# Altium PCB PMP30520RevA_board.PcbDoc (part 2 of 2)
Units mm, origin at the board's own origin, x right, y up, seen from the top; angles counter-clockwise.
Board outline 53.34 x 64.26 mm, 2 copper layers (Top Layer, Bottom Layer), stack 1.575 mm thick; 53 components, 27 nets, 127 pads, 140 vias.
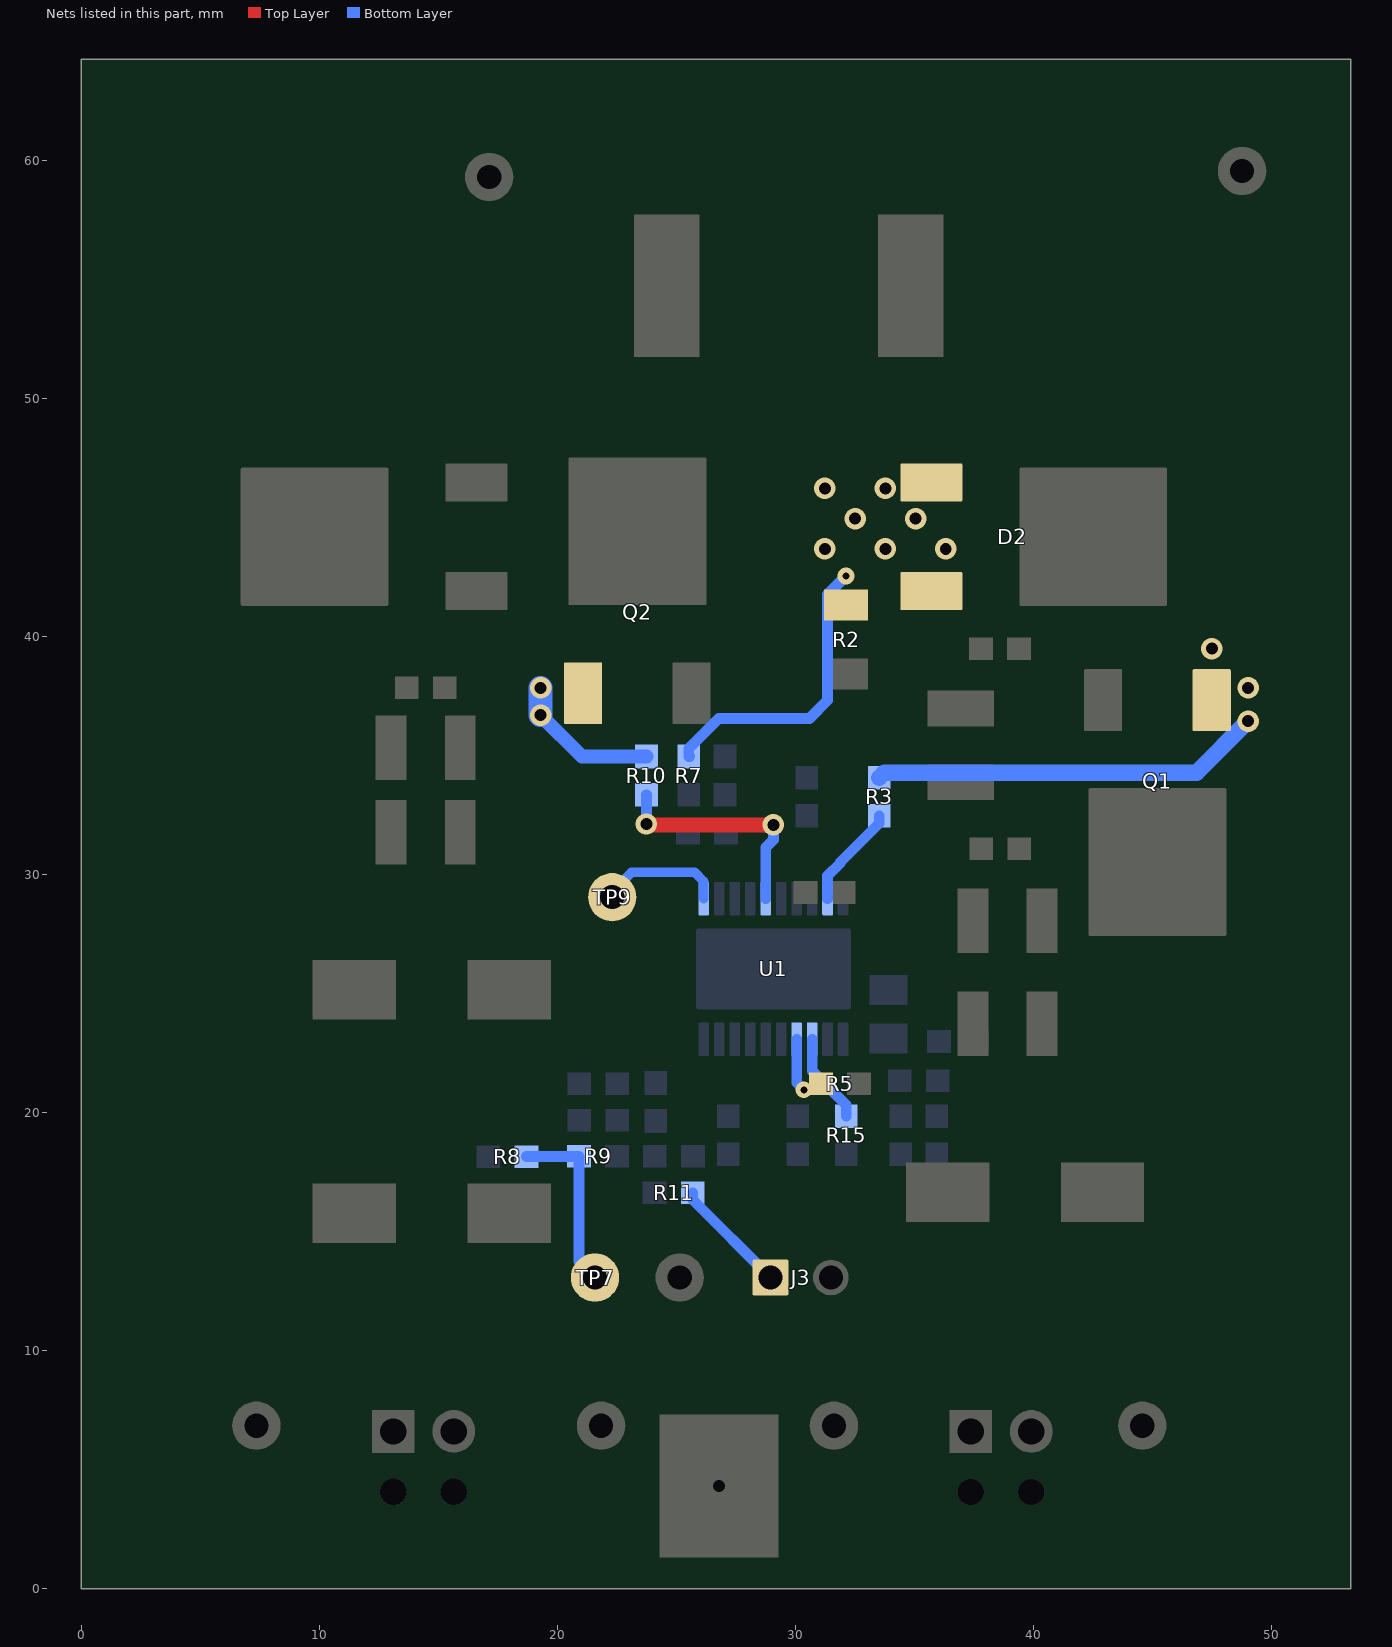
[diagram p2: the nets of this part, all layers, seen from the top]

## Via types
v1: diameter 0.9, hole 0.5, Top Layer to Bottom Layer, 60 vias
v2: diameter 0.7, hole 0.3, Top Layer to Bottom Layer, 34 vias
v3: diameter 0.9, hole 0.5, Top Layer to Bottom Layer, tented top, 25 vias
v4: diameter 0.6, hole 0.3, Top Layer to Bottom Layer, 9 vias
v5: diameter 0.6, hole 0.3, Top Layer to Bottom Layer, tented both sides, 6 vias
v6: diameter 0.9, hole 0.5, Top Layer to Bottom Layer, tented bottom, 2 vias
v7: diameter 0.7, hole 0.3, Top Layer to Bottom Layer, tented both sides, 2 vias
v8: diameter 0.7, hole 0.3, Top Layer to Bottom Layer, tented bottom, 1 vias
v9: diameter 0.9, hole 0.5, Top Layer to Bottom Layer, tented both sides, 1 vias

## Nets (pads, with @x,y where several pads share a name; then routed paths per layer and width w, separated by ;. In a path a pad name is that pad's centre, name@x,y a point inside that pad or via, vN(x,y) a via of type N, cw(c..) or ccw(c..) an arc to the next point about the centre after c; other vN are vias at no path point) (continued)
NetD2_1: D2.1 D2.3 R2.1 R7.2 | length 12.6
  Bottom Layer w0.45: R7.2@25.565,34.963 R7.2@25.527,34.963 25.527,35.306 26.787,36.566 30.597,36.566 31.356,37.325 31.356,41.77 v2(32.131,42.545)
  other v1: 31.242,43.688 33.782,43.688 36.322,43.688 32.512,44.958 35.052,44.958 31.242,46.228
  other v3: 33.782,46.228
NetJ3_1: J3.1 R11.2 | length 4.9
  Bottom Layer w0.45: R11.2@25.692,16.637 25.692,16.345 J3.1@28.956,13.081
NetQ1_1: Q1.1 R3.2 | length 16.5
  Bottom Layer w0.7: R3.2@33.528,34.074 33.744,34.29 46.863,34.29 v1(49.022,36.449)
  other v1: 49.022,37.846 47.498,39.497
NetQ2_1: Q2.1 R10.1 | length 6.3
  Bottom Layer w0.6: v1(19.304,36.703) 21.044,34.963 R10.1@23.749,34.963
  Bottom Layer w1: v1(19.304,36.703) v1(19.304,37.846)
NetR3_1: R3.1 U1.19 | length 4.4
  Bottom Layer w0.45: U1.19@31.358,28.993 31.358,29.961 31.885,30.488 31.885,30.521 33.528,32.164 R3.1@33.528,32.474
NetR5_1: R5.1 U1.4 | length 3.1
  Top Layer w0.45: v7(30.361,20.963) 30.823,20.963 R5.1@31.077,21.217
  Bottom Layer w0.45: U1.4@30.058,23.093 30.058,21.266 v7(30.361,20.963)
NetR8_1: R8.1 R9.2 TP7.1 | length 7.6
  Bottom Layer w0.45: R8.1@18.707,18.161 20.909,18.161 R9.2@20.917,18.169 20.917,13.754 TP7.1@21.59,13.081
NetR10_2: R10.2 U1.15 | length 9.8
  Top Layer w0.635: v1(23.749,32.131) 23.787,32.093 v1(29.083,32.093)
  Bottom Layer w0.45: v1(23.749,32.131) R10.2@23.749,33.363 ; U1.15@28.758,28.993 28.758,31.145 29.083,31.47 v1(29.083,32.093)
NetR15_2: R15.2 U1.3 | length 3.8
  Bottom Layer w0.45: U1.3@30.708,23.093 30.708,21.759 32.139,20.328 R15.2@32.139,19.858
NetTP9_1: TP9.1 U1.11 | length 5.3
  Bottom Layer w0.4: TP9.1@22.313,29.059 22.313,29.298 23.114,30.099 25.781,30.099 26.158,29.722 U1.11@26.158,28.993
pads on no net: J1.MH1 J1.MH2 J2.MH1 J2.MH2 U1.21@29.083,26.043

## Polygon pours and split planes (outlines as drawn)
NetC4_1 on Top Layer "TOP_LAYER_NETC4_1_P006" (solid, remove dead copper, pour order 6): 30.734,49.911 ccw(c32.258,49.911) 32.258,48.387 37.465,48.387 cw(c37.452,46.999) 38.839,46.986 cw(c37.465,46.736) 38.862,46.736 38.862,40.359 38.862,36.576 ccw(c39.751,36.576) 39.751,35.687 41.656,35.687 44.196,35.687 45.085,35.687 ccw(c45.085,36.195) 45.593,36.195 45.593,40.259 cw(c46.609,40.259) 46.609,41.275 48.641,41.275 ccw(c48.641,43.434) 50.8,43.434 50.8,59.309 ccw(c48.514,59.309) 48.514,61.595 33.02,61.595 ccw(c33.02,59.309) 30.734,59.309
NetQ2_1 on Top Layer "TOP_LAYER_NETQ2_1_P018" (solid, remove dead copper, pour order 18): 22.098,39.243 22.098,35.941 18.669,35.941 18.669,39.243
NetQ1_1 on Top Layer "TOP_LAYER_NETQ1_1_P042" (solid, remove dead copper, pour order 42): 47.371,35.814 46.986,35.814 cw(c46.982,36.187) 46.609,36.182 46.609,39.624 cw(c47.244,39.624) 47.244,40.259 47.371,40.259 50.038,40.259 cw(c50.038,39.497) 50.8,39.497 50.8,36.83 cw(c49.784,36.83) 49.784,35.814 49.53,35.814
NetC2_1 on Top Layer "TOP_LAYER_NETC2_1_P002" (solid, remove dead copper, pour order 2): 14.224,2.667 2.54,2.667 2.54,61.595 14.224,61.595 14.224,38.481 14.224,6.529
NetD1_1 on Top Layer "TOP_LAYER_NETD1_1_P004" (solid, remove dead copper, pour order 4): 17.78,61.595 ccw(c17.78,59.055) 15.24,59.055 15.24,41.021 ccw(c16.129,41.021) 16.129,40.132 26.416,40.132 28.067,40.132 ccw(c28.067,41.783) 29.718,41.783 29.718,59.055 ccw(c27.178,59.055) 27.178,61.595
NetD2_1 on Top Layer "TOP_LAYER_NETD2_1_P012" (solid, remove dead copper, pour order 12): 37.616,46.609 ccw(c36.854,46.609) 36.854,47.371 32.258,47.371 31.487,47.362 ccw(c31.487,46.609) 30.734,46.609 30.734,41.275 ccw(c31.369,41.275) 31.369,40.64 36.83,40.64 ccw(c36.83,41.426) 37.616,41.426
NetC1_1 on Top Layer "TOP_LAYER_NETC1_1_P016" (solid, remove dead copper, pour order 16): 38.862,34.671 50.8,34.671 50.8,2.667 38.862,2.667
GND on Top Layer "TOP_LAYER_GND_P020" (solid, remove dead copper, pour order 20): 38.354,2.667 38.354,34.671 34.925,34.671 34.925,39.243 14.732,39.243 14.732,33.909 14.732,4.953 14.732,2.667
NetC4_2 on Top Layer "TOP_LAYER_NETC4_2_P028" (solid, remove dead copper, pour order 28): 38.346,36.195 35.56,36.195 35.56,40.222 38.346,40.222 38.346,38.608
NetD1_1 on Bottom Layer "BOTTOM_LAYER_NETD1_1_P060" (solid, remove dead copper, pour order 60): 17.78,61.595 ccw(c17.78,59.055) 15.24,59.055 15.24,41.021 ccw(c16.129,41.021) 16.129,40.132 26.416,40.132 28.067,40.132 ccw(c28.067,41.783) 29.718,41.783 29.718,59.055 ccw(c27.178,59.055) 27.178,61.595
NetD2_1 on Bottom Layer "BOTTOM_LAYER_NETD2_1_P058" (solid, remove dead copper, pour order 58): 37.616,46.609 ccw(c36.854,46.609) 36.854,47.371 32.258,47.371 31.487,47.362 ccw(c31.487,46.609) 30.734,46.609 30.734,41.275 ccw(c31.369,41.275) 31.369,40.64 36.83,40.64 ccw(c36.83,41.426) 37.616,41.426
NetC4_1 on Bottom Layer "BOTTOM_LAYER_NETC4_1_P056" (solid, remove dead copper, pour order 56): 30.734,49.911 ccw(c32.258,49.911) 32.258,48.387 37.465,48.387 cw(c37.452,46.999) 38.839,46.986 cw(c37.465,46.736) 38.862,46.736 38.862,40.359 38.862,36.576 ccw(c39.751,36.576) 39.751,35.687 41.656,35.687 44.196,35.687 45.085,35.687 ccw(c45.085,36.195) 45.593,36.195 45.593,40.259 cw(c46.609,40.259) 46.609,41.275 49.022,41.275 cw(c49.022,40.259) 50.038,40.259 ccw(c50.038,41.021) 50.8,41.021 50.8,43.688 50.8,59.309 ccw(c48.514,59.309) 48.514,61.595 33.02,61.595 ccw(c33.02,59.309) 30.734,59.309
NetQ1_1 on Bottom Layer "BOTTOM_LAYER_NETQ1_1_P050" (solid, remove dead copper, pour order 50): 46.6,36.2 ccw(c46.986,36.2) 46.986,35.814 48.387,35.814 ccw(c48.387,36.449) 49.022,36.449 49.022,39.869 ccw(c48.637,39.874) 48.641,40.259 47.244,40.259 ccw(c47.244,39.615) 46.6,39.615
NetC16_2 on Bottom Layer "BOTTOM_LAYER_NETC16_2_P022" (solid, remove dead copper, pour order 22): 24.701,17.653 24.701,20.152 22.034,20.152 22.034,17.653
GND on Bottom Layer "BOTTOM_LAYER_GND_P024" (solid, remove dead copper, pour order 24): 34.925,39.243 34.925,34.671 38.354,34.671 38.354,8.382 14.732,8.382 14.732,39.243
GND on Bottom Layer "BOTTOM_LAYER_GND_P026" (solid, remove dead copper, pour order 26): 21.971,24.333 21.971,27.737 36.195,27.737 36.195,24.333
NetC1_1 on Bottom Layer "BOTTOM_LAYER_NETC1_1_P030" (solid, remove dead copper, pour order 30): 38.862,34.674 50.927,34.674 50.927,2.67 38.862,2.67
NetC2_1 on Bottom Layer "BOTTOM_LAYER_NETC2_1_P038" (solid, remove dead copper, pour order 38): 14.224,2.667 2.54,2.667 2.54,61.595 14.224,61.595 14.224,38.481 14.224,6.529

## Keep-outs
Keep-Out Layer:
  text ".Layer_Name" at 14.656,-21.806 h1.52

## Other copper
Top Layer:
  rectangle net NetC4_2: 35.56,36.195 38.354,40.222
  text ".Layer_Name" at 14.656,-21.806 h1.52
Bottom Layer:
  region net NetQ1_1: 49.022,35.814 ccw(c49.022,36.322) 49.53,36.322 49.53,39.649 ccw(c48.92,39.649) 48.92,40.259 48.006,40.259 48.006,36.576 ccw(c48.768,36.576) 48.768,35.814
  pour cut-out: 25.604,24.181 32.715,24.181 32.715,23.623 25.606,23.623
  pour cut-out: 25.629,28.575 25.629,27.889 32.995,27.889 32.995,28.559
  pour cut-out: 28.542,35.306 31.623,35.306 32.893,36.576 32.893,38.1 31.75,38.1 30.099,36.449 27.051,36.449 27.051,34.765 27.526,34.29
  text ".Layer_Name" at 14.656,-21.806 h1.52

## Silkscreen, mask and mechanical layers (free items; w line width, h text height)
Top Overlay:
  lines w0.254: 32.765,13.081 34.29,13.081 34.29,11.43 ; 33.401,11.43 35.179,11.43 ; 33.655,11.049 34.925,11.049 ; 33.909,10.668 34.671,10.668
  text "'.PRJ_Number''.PCB_Rev'" at 51.689,5.207 h2 r90
  text "+VOUT" at 2.413,0.635 h1.52
  text "+VIN" at 43.434,0.635 h1.52
  text ".Layer_Name" at 14.656,-21.806 h1.52
Bottom Overlay:
  text ".Layer_Name" at 14.656,-21.806 h1.52
Top Paste:
  text ".Layer_Name" at 14.656,-21.806 h1.52
Bottom Paste:
  text ".Layer_Name" at 14.656,-21.806 h1.52
Top Solder:
  text ".Layer_Name" at 14.656,-21.806 h1.52
  text ".Layer_Name" at 14.656,-21.806 h1.52
Bottom Solder:
  text "'.PRJ_Number''.PCB_Rev'" at 35.052,8.763 h2
  text ".Layer_Name" at 14.656,-21.806 h1.52
Drill Guide:
  text ".Layer_Name" at 14.656,-21.806 h1.52
M1 Board Outline:
  the board outline again, w0.254
  text ".Layer_Name" at 14.656,-21.806 h1.52
M2 Board Dimensions:
  rectangle: 3.175,-10.16 12.7,-6.985
  rectangle: 0,-6.985 3.175,-3.81
  lines w0.178: 0,-6.985 25.4,-6.985 ; 3.175,-10.16 3.175,-3.81 ; 6.35,-10.16 6.35,-3.81 ; 12.7,-10.16 12.7,-3.81 ; 19.05,-10.16 19.05,-3.81 ; 0,-10.16 0,-3.81 25.4,-3.81 25.4,-10.16 0,-10.16
  text "'.Print_Date'" at 1.778,64.77 h1.52
  text "'.Print_Time'" at 16.891,64.77 h1.52
  text ".Layer_Name" at 14.656,-21.806 h1.52
M3 3D STEP Top:
  text ".Layer_Name" at 14.656,-21.806 h1.52
M4 3D STEP Bottom:
  text ".Layer_Name" at 14.656,-21.806 h1.52
M5 Assembly Top:
  lines w0.254: -7.417,-23.626 160.223,-23.626 ; -7.417,-18.462 160.274,-18.462 ; -7.417,-13.297 -7.417,-28.791 94.31,-28.791 160.274,-28.791 160.274,-13.297 -7.404,-13.297 -7.404,-28.791 32.614,-28.791 ; 55.194,-28.791 55.194,-13.297 ; 87.376,-18.462 87.376,-13.297 ; 108.712,-18.462 108.712,-13.297 ; 124.511,-28.956 124.511,-23.804
  text "COMPONENTS MARKED 'DNP' SHOULD NOT BE POPULATED." at 29.299,-8.09 h1.52
  text "ASSEMBLY VARIANT:" at 29.286,-11.024 h1.52
  text ".VariantName" at 55.601,-11.024 h1.52
  text "PCB VIEWED FROM TOP SIDE" at -5.804,-16.654 h1.52
  text "BOARD #:" at 57.099,-16.654 h1.52
  text ".PRJ_Number" at 70.955,-16.654 h1.52
  text "REV:" at 92.405,-16.654 h1.52
  text ".PCB_Rev" at 99.809,-16.654 h1.52
  text "SVN REV:" at 113.69,-16.654 h1.52
  text ".VersionControl_RevNumber" at 126.543,-16.654 h1.52
  text "TID #:" at 57.099,-21.819 h1.52
  text ".TID" at 70.955,-21.819 h1.52
  text "PLOT NAME =" at -5.804,-27.034 h1.52
  text ".plot_File_Name" at 14.656,-27.034 h1.52
  text "GENERATED    :" at 57.15,-27.034 h1.52
  text ".Print_Date" at 79.235,-27.034 h1.52
  text ".Print_Time" at 97.752,-27.034 h1.52
  text "TEXAS INSTRUMENTS" at 129.87,-27.034 h1.52
M6 Assembly Bottom:
  lines w0.254: -7.429,-18.474 160.261,-18.474 ; -7.379,-23.639 160.261,-23.639 ; 28.334,-28.969 28.334,-23.817 ; 44.133,-18.474 44.133,-13.31 ; 65.468,-18.474 65.468,-13.31 ; 97.65,-28.804 97.65,-13.31 ; 120.231,-28.804 160.249,-28.804 160.249,-13.31 -7.429,-13.31 -7.429,-28.804 58.534,-28.804 160.261,-28.804 160.261,-13.31
  text "COMPONENTS MARKED 'DNP' SHOULD NOT BE POPULATED." at 154.991,-8.077 h1.52
  text ".VariantName" at 128.473,-11.024 h1.52
  text "ASSEMBLY VARIANT:" at 154.864,-11.024 h1.52
  text ".VersionControl_RevNumber" at 26.302,-16.667 h1.52
  text "SVN REV:" at 39.154,-16.667 h1.52
  text ".PCB_Rev" at 53.035,-16.667 h1.52
  text "REV:" at 60.439,-16.667 h1.52
  text ".PRJ_Number" at 81.89,-16.667 h1.52
  text "BOARD #:" at 95.745,-16.667 h1.52
  text "PCB VIEWED FROM BOTTOM SIDE" at 158.648,-16.667 h1.52
  text ".TID" at 81.89,-21.831 h1.52
  text "TID #:" at 95.745,-21.831 h1.52
  text "TEXAS INSTRUMENTS" at 22.974,-27.047 h1.52
  text ".Print_Time" at 55.093,-27.047 h1.52
  text ".Print_Date" at 73.609,-27.047 h1.52
  text "GENERATED    :" at 95.694,-27.047 h1.52
  text ".plot_File_Name" at 138.189,-27.047 h1.52
  text "PLOT NAME =" at 158.648,-27.047 h1.52
M9 Title Sheet:
  drawing of 57 lines, arcs and shapes, not listed
  text "1" at 18.792,204.127 h1.78
  text "2" at 82.182,204.127 h1.78
  text "3" at 145.411,204.127 h1.78
  text "4" at 209.08,204.127 h1.78
  text "5" at 272.555,204.127 h1.78
  text "6" at 336.182,204.127 h1.78
  text "A" at -10.579,175.095 h1.78
  text "A" at 365.341,175.095 h1.78
  text "B" at -10.579,114.643 h1.78
  text "B" at 365.341,114.643 h1.78
  text "C" at -10.579,54.318 h1.78
  text "C" at 365.341,54.318 h1.78
  text "PROJECT TITLE:" at 288.125,7.048 h1.14
  text ".PRJ_Title" at 289.395,3.662 h1.78
  text "DESIGNED FOR:" at 288.125,-0.597 h1.14
  text ".PRJ_Customer" at 289.395,-4.153 h1.78
  text "D" at -10.579,-5.88 h1.78
  text "D" at 365.341,-5.88 h1.78
  text "FILE NAME:" at 288.125,-8.217 h1.14
  text ".PCB_File_Name_No_Path" at 289.395,-11.265 h1.78
  text "Texas Instruments (TI) and/or its licensors do not warrant the accuracy or completeness of this specification" at 161.9,-15.376 h1.14
  text "ENGINEER:" at 288.125,-15.583 h1.14
  text "LAYOUT BY:" at 326.352,-15.583 h1.14
  text "or any information contained therein. TI and/or its licensors do not warrant that this design will meet" at 160.757,-18.237 h1.14
  text ".PRJ_Engineer" at 289.395,-19.52 h1.78
  text ".PCB_Layout" at 327.635,-19.52 h1.78
  text "the specifications, will be suitable for your application or fit for any particular purpose, or will operate in" at 160.757,-21.099 h1.14
  text ".Layer_Name" at 14.656,-21.806 h1.52
  text "ALTIUM DESIGNER VERSION:" at 326.352,-23.457 h1.14
  text "an implementation. TI and/or its licensors do not warrant that the design is production worthy. You should" at 160.757,-23.961 h1.14
  text "completely validate and test your design implementation to confirm the system functionality for your application." at 161.9,-26.822 h1.14
  text ".print_Scale" at 289.395,-26.843 h1.78
  text ".Application_BuildNumber" at 327.635,-26.843 h1.78
  text "1" at 18.792,-32.093 h1.78
  text "2" at 82.182,-32.093 h1.78
  text "3" at 145.411,-32.093 h1.78
  text "4" at 209.08,-32.093 h1.78
  text "5" at 272.555,-32.093 h1.78
  text "6" at 336.182,-32.093 h1.78
M10 Fab Notes:
  drawing of 189 lines, arcs and shapes, not listed
  text "DESIGN INFORMATION" at 314.503,161.447 h1.52
  text "MIN. TRACK WIDTH:" at 298.131,158.091 h1.52
  text "8" at 325.976,158.091 h1.52
  text "MIL" at 329.907,158.091 h1.52
  text "MIN. CLEARANCE:" at 298.131,154.938 h1.52
  text "0.2" at 324.452,154.938 h1.52
  text "mm" at 329.907,154.938 h1.52
  text "MIN. VIA PAD SIZE:" at 298.131,151.785 h1.52
  text "24" at 325.214,151.785 h1.52
  text "MIL" at 329.907,151.785 h1.52
  text "0.05mm (2MIL)" at 315.784,148.486 h1.52
  text "MINIMUM ANNULAR RING" at 289.769,148.277 h1.52
  text "EXTERNAL" at 333.768,148.277 h1.52
  text "PER" at 294.849,145.48 h1.52
  text "IPC-D-275 CLASS 2 LEVEL C" at 300.437,145.48 h1.52
  text "MIL, HOLES" at 338.238,142.928 h1.52
  text "+/-" at 328.27,142.709 h1.52
  text "+/-" at 349.961,142.709 h1.52
  text "REGISTRATION TOLERANCES:" at 289.769,142.682 h1.52
  text "METAL" at 320.243,142.682 h1.52
  text "5" at 334.879,142.683 h1.52
  text "3" at 356.037,142.683 h1.52
  text "MIL" at 358.99,142.682 h1.52
  text "HOLE SIZE TOLERANCE (UNLESS OTHERWISE SPECIFIED):" at 289.769,140.185 h1.52
  text "+/-" at 349.961,140.112 h1.52
  text "3" at 356.037,140.085 h1.52
  text "MIL" at 358.99,140.085 h1.52
  text "MATERIAL:" at 287.87,136.589 h1.52
  text "FR-4 High Tg" at 312.926,133.324 h1.52
  text "X" at 309.257,133.122 h1.52
  text "FR-408" at 298.563,133.007 h1.52
  text "OTHER" at 336.358,133.007 h1.52
  text "62 MIL (1.6mm) +/-10%" at 306.694,129.374 h1.52
  text "X" at 303.643,129.312 h1.52
  text "THICKNESS:" at 289.769,129.165 h1.52
  text "OTHER" at 339.33,129.165 h1.52
  text "TOLERANCE:" at 289.769,125.652 h1.52
  text "X" at 311.314,125.652 h1.52
  text "ANSI IPC-6012 TYPE 3 CLASS 2" at 315.836,125.652 h1.52
  text "OTHER +/-" at 315.835,121.989 h1.52
  text "BOW & TWIST:" at 289.769,118.302 h1.52
  text "X" at 311.314,118.302 h1.52
  text "ANSI IPC-6012 TYPE 3 CLASS 2" at 315.836,118.302 h1.52
  text "OTHER +/-" at 315.835,114.576 h1.52
  text "DRILLING:" at 287.87,111.258 h1.52
  text "NC_DRILL FILES" at 332.599,108.586 h1.52
  text "REFERENCE:" at 289.769,108.486 h1.52
  text "X" at 306.463,108.484 h1.52
  text "AS SHOWN" at 310.984,108.486 h1.52
  text "X" at 329.348,108.486 h1.52
  text "OTHER" at 340.168,104.873 h1.52
  text "PTH COPPER THICKNESS:" at 289.761,104.783 h1.52
  text "X" at 318.697,104.783 h1.52
  text "20-30 um" at 321.948,104.783 h1.52
  text "BOARD FINISH:" at 287.87,101.034 h1.52
  text "SILKSCREEN:" at 291.812,98.237 h1.52
  text "X" at 316.14,98.237 h1.52
  text "TOP" at 319.112,98.237 h1.52
  text "X" at 329.094,98.237 h1.52
  text "BOTTOM" at 332.091,98.237 h1.52
  text "SILKSCREEN COLOR:" at 291.812,94.295 h1.52
  text "X" at 316.115,94.295 h1.52
  text "WHITE" at 319.112,94.295 h1.52
  text "OTHER" at 332.091,94.295 h1.52
  text "X" at 319.442,90.652 h1.52
  text "GREEN" at 322.439,90.652 h1.52
  text "OTHER" at 338.136,90.652 h1.52
  text "SOLDER RESIST COLOR:" at 291.812,90.477 h1.52
  text "X" at 319.442,86.734 h1.52
  text "MATTE" at 322.439,86.734 h1.52
  text "SEMI-GLOSS" at 338.125,86.717 h1.52
  text "IMMERSION GOLD (ENIG)" at 314.819,82.345 h1.52
  text "ENEPIG" at 348.793,82.162 h1.52
  text "SURFACE FINISH:" at 287.87,82.136 h1.52
  text "X" at 310.298,82.136 h1.52
  text "IMM. TIN/SILVER OR EQUIV" at 296.24,78.649 h1.52
  text "OTHER" at 332.599,78.549 h1.52
  text "ARRAY/PANEL:" at 287.87,74.602 h1.52
  text "CUT AND TRIM PER M1 BOARD OUTLINE" at 314.819,74.393 h1.52
  text "N.C. ROUTE" at 314.819,70.94 h1.52
  text "X" at 332.295,70.94 h1.52
  text "V. SCORE" at 336.816,70.94 h1.52
  text "CERTIFICATION:" at 287.87,67.66 h1.52
  text "MATERIALS AND WORKMANSHIP FOR ALL PCBS" at 306.285,67.66 h1.52
  text "TO MEET OR EXCEED THE REQUIREMENTS OF:" at 306.285,65.271 h1.52
  text "X" at 297.078,62.003 h1.52
  text "ANSI IPC-A-600F CLASS ->" at 300.329,62.003 h1.52
  text "X" at 342.188,62.003 h1.52
  text "2" at 344.982,62.003 h1.52
  text "1" at 336.981,61.965 h1.52
  text "3" at 353.973,61.965 h1.52
  text "X" at 317.702,58.252 h1.52
  text "RoHS" at 320.953,58.252 h1.52
  text "OTHER" at 337.321,58.252 h1.52
  text "PER ORDER" at 347.407,58.252 h1.52
  text "ALL BOARDS MUST MEET OR EXCEED UL94-V0 REQUIREMENTS." at 288.569,54.345 h1.52
  text "PCB MUST BEAR THE UL94V-0 UL REGISTERED MATERIAL ID NUMBER" at 288.569,51.397 h1.52
  text "ADDITIONAL REQUIREMENTS:" at 287.87,47.094 h1.52
  text "MICROSECTION:" at 289.769,44.373 h1.52
  text "YES" at 312.775,44.373 h1.52
  text "REQUIRED" at 334.657,40.707 h1.52
  text "BARE BOARD ELEC. TEST:" at 289.769,40.634 h1.52
  text "NONE" at 322.935,40.634 h1.52
  text "X" at 331.66,40.634 h1.52
  text "PER ORDER" at 349.693,40.634 h1.52
  text "XX MIL VIAS REQUIRE NON-CONDUCTIVE FILL AND PLANARIZE" at 294.04,35.428 h1.5
  text "XX MIL VIAS REQUIRE CONDUCTIVE FILL AND PLANARIZE" at 294.243,32.787 h1.52
  text "OUTER XX MIL VIAS REQUIRE 50 OHM SINGLE-ENDED IMPEDANCE" at 294.218,28.637 h1.47
  text "LAYER 2 & 3 (INNER LAYERS) XX MIL WIDE, XX MIL SPACE / TRACES REQUIRE 100 OHM DIFFERENTIAL IMPEDANCE" at 294.015,22.65 h1.52
  text ".Layer_Name" at 152.927,8.535 h1.52
  text ".Layer_Name" at 14.656,-21.806 h1.52
M11 Gerber Information:
  lines w0.254: -7.417,-23.626 160.223,-23.626 ; -7.417,-18.462 160.274,-18.462 ; -7.417,-13.297 -7.417,-28.791 94.31,-28.791 160.274,-28.791 160.274,-13.297 -7.404,-13.297 -7.404,-28.791 32.614,-28.791 ; 55.194,-28.791 55.194,-13.297 ; 87.376,-18.462 87.376,-13.297 ; 108.712,-18.462 108.712,-13.297 ; 124.511,-28.956 124.511,-23.804
  text "ALL ARTWORK VIEWED FROM TOP SIDE" at -5.804,-16.654 h1.52
  text "BOARD #:" at 57.099,-16.654 h1.52
  text ".PRJ_Number" at 70.955,-16.654 h1.52
  text "REV:" at 92.405,-16.654 h1.52
  text ".PCB_Rev" at 99.809,-16.654 h1.52
  text "SVN REV:" at 113.69,-16.654 h1.52
  text ".VersionControl_RevNumber" at 126.543,-16.654 h1.52
  text "LAYER NAME =" at -5.804,-21.806 h1.52
  text "TID #:" at 57.099,-21.819 h1.52
  text ".TID" at 70.955,-21.819 h1.52
  text "PLOT NAME =" at -5.804,-27.034 h1.52
  text ".plot_File_Name" at 14.656,-27.034 h1.52
  text "GENERATED    :" at 57.15,-27.034 h1.52
  text ".Print_Date" at 79.235,-27.034 h1.52
  text ".Print_Time" at 97.752,-27.034 h1.52
  text "TEXAS INSTRUMENTS" at 129.87,-27.034 h1.52
M12 Stackup:
  drawing of 191 lines, arcs and shapes, not listed
  text "Layer" at 249.119,198.31 h1.52
  text "Name" at 259.531,198.31 h1.52
  text "Material" at 283.147,198.31 h1.52
  text "Thickness" at 304.985,198.31 h1.52
  text "Constant" at 321.49,198.31 h1.52
  text "Board Layer Stack" at 335.965,198.31 h1.52
  text "Top Overlay" at 259.531,195.262 h1.52
  text "Top Solder" at 259.531,192.214 h1.52
  text "Solder Resist" at 283.147,192.214 h1.52
  text "0.40mil" at 304.985,192.214 h1.52
  text "3.5" at 321.49,192.214 h1.52
  text "1" at 249.119,189.166 h1.52
  text "Top Layer" at 259.531,189.166 h1.52
  text "Copper" at 283.147,189.166 h1.52
  text "1.40mil" at 304.985,189.166 h1.52
  text "Dielectric1" at 259.531,186.118 h1.52
  text "FR-4" at 283.147,186.118 h1.52
  text "59.20mil" at 304.985,186.118 h1.52
  text "4.8" at 321.49,186.118 h1.52
  text "2" at 249.119,183.07 h1.52
  text "Bottom Layer" at 259.531,183.07 h1.52
  text "Copper" at 283.147,183.07 h1.52
  text "1.40mil" at 304.985,183.07 h1.52
  text "Bottom Solder" at 259.531,180.022 h1.52
  text "Solder Resist" at 283.147,180.022 h1.52
  text "0.40mil" at 304.985,180.022 h1.52
  text "3.5" at 321.49,180.022 h1.52
  text "Bottom Overlay" at 259.531,176.975 h1.52
  text ".Layer_Name" at 14.656,-21.806 h1.52
M13 Component Bodies Top:
  text ".Layer_Name" at 14.656,-21.806 h1.52
M14 Component Bodies Bottom:
  text ".Layer_Name" at 14.656,-21.806 h1.52
M15 Courtyards Top:
  text ".Layer_Name" at 14.656,-21.806 h1.52
M16 Courtyards Bottom:
  text ".Layer_Name" at 14.656,-21.806 h1.52
Drill Drawing:
  circle w0.254: c136.241,70.46 r0.703
  lines w0.254: 135.538,72.92 136.944,72.92 136.944,74.325 135.538,74.325 135.538,72.92 ; 135.538,76.082 136.241,76.433 136.944,76.082 136.593,76.785 136.944,77.487 136.241,77.136 135.538,77.487 135.89,76.785 135.538,76.082 ; 135.538,79.596 135.89,79.596 135.89,79.244 136.593,79.244 136.593,79.596 136.944,79.596 136.944,80.298 136.593,80.298 136.593,80.65 135.89,80.65 135.89,80.298 135.538,80.298 135.538,79.596 ; 135.538,83.812 136.944,83.812 136.241,82.406 135.538,83.812
  lines w0.305: 134.264,68.809 216.362,68.809 ; 134.264,84.62 216.362,84.62 ; 142.85,65.646 142.85,87.782 ; 151.287,65.646 151.287,87.782 ; 167.453,65.646 167.453,87.782 ; 174.037,65.646 174.037,87.782 ; 183.568,65.646 183.568,87.782 ; 201.972,65.646 201.972,87.782 ; 134.264,65.646 216.362,65.646 216.362,87.782 134.264,87.782 134.264,65.646
  text "Symbol" at 136.162,85.569 h1.83
  text "Quantity" at 143.799,85.569 h1.83
  text "Finished Hole Size" at 152.235,85.569 h1.83
  text "Plated" at 168.402,85.569 h1.83
  text "Hole Type" at 174.986,85.569 h1.83
  text "Drill Layer Pair" at 184.517,85.569 h1.83
  text "Hole Tolerance" at 202.92,85.569 h1.83
  text "4" at 143.799,82.406 h1.52
  text "43.31mil (1.100mm)" at 152.235,82.406 h1.52
  text "NPTH" at 168.402,82.406 h1.52
  text "Round" at 174.986,82.406 h1.52
  text "Top Layer - Bottom Layer" at 184.517,82.406 h1.52
  text "52" at 143.799,79.244 h1.52
  text "11.81mil (0.300mm)" at 152.235,79.244 h1.52
  text "PTH" at 168.402,79.244 h1.52
  text "Round" at 174.986,79.244 h1.52
  text "Top Layer - Bottom Layer" at 184.517,79.244 h1.52
  text "89" at 143.799,76.082 h1.52
  text "19.69mil (0.500mm)" at 152.235,76.082 h1.52
  text "PTH" at 168.402,76.082 h1.52
  text "Round" at 174.986,76.082 h1.52
  text "Top Layer - Bottom Layer" at 184.517,76.082 h1.52
  text "11" at 143.799,72.92 h1.52
  text "40.00mil (1.016mm)" at 152.235,72.92 h1.52
  text "PTH" at 168.402,72.92 h1.52
  text "Round" at 174.986,72.92 h1.52
  text "Top Layer - Bottom Layer" at 184.517,72.92 h1.52
  text "4" at 143.799,69.757 h1.52
  text "43.31mil (1.100mm)" at 152.235,69.757 h1.52
  text "PTH" at 168.402,69.757 h1.52
  text "Round" at 174.986,69.757 h1.52
  text "Top Layer - Bottom Layer" at 184.517,69.757 h1.52
  text "160 Total" at 143.799,66.595 h1.52
  text ".Layer_Name" at 14.656,-21.806 h1.52
M17 Embedded Cavity:
  text ".Layer_Name" at 14.656,-21.806 h1.52
M18 Embedded Assembly:
  text ".Layer_Name" at 14.656,-21.806 h1.52
M19 Embedded Keepout:
  text ".Layer_Name" at 14.656,-21.806 h1.52

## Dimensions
0,0 to 53.34,0 on M2 Board Dimensions
0,0 to 0,64.262 on M2 Board Dimensions
0,-10.16 to 25.4,-10.16 on M2 Board Dimensions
